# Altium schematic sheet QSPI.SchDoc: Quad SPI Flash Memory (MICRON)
size A4; Date: 29-OCT-2015; Author: A.B; CompanyName: STMicroelectronics; Organization: MCD/TOOLS/GNB; Address1: 12, Rue Jules HOROWITZ; Address2: 38019 Grenoble; Address3: FRANCE; DocumentNumber: MB1225; Revision: B-01; SheetNumber: 6; SheetTotal: 12; Project: STM32F769I-DISCO
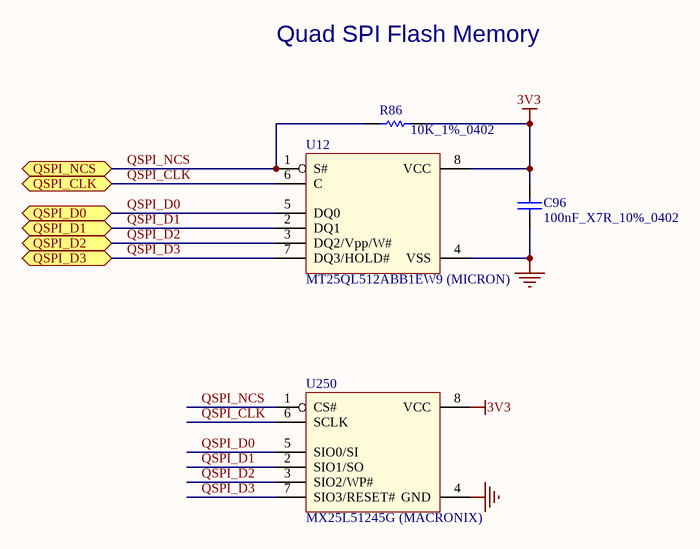
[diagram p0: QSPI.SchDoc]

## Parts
C96  100nF_X7R_10%_0402  [0402C]
R86  10K_1%_0402  [0402R]
U12  MT25QL512ABB1EW9 (MICRON)  [DFN8_1R27_6X8_TP4R8X5R16]
U250  MX25L51245G (MACRONIX)  [SON8_1R27_6X8]

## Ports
QSPI_CLK, QSPI_D0, QSPI_D1, QSPI_D2, QSPI_D3, QSPI_NCS

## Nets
3V3: C96.2 R86.2 U12.8(VCC) U250.8(VCC)
GND: C96.1 U12.4(VSS) U250.4(GND)
QSPI_CLK: U12.6(C) U250.6(SCLK) ; port QSPI_CLK
QSPI_D0: U12.5(DQ0) U250.5(SIO0/SI) ; port QSPI_D0
QSPI_D1: U12.2(DQ1) U250.2(SIO1/SO) ; port QSPI_D1
QSPI_D2: U12.3(DQ2/Vpp/W#) U250.3(SIO2/WP#) ; port QSPI_D2
QSPI_D3: U12.7(DQ3/HOLD#) U250.7(SIO3/RESET#) ; port QSPI_D3
QSPI_NCS: R86.1 U12.1(S#) U250.1(CS#) ; port QSPI_NCS

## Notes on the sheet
- Quad SPI Flash Memory

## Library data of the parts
C96 = Cap_100nF_X7R_10%_0402: Capacitor,100nF,16V,X7R,10%,0402,YAGEO; Manuf_Part_1: CC0402KRX7R7BB104
R86 = Res_10K_1%_0402: Resistor,10K,0402,1%,YAGEO; Manuf_Part_1: RC0402FR-0710KL
U12 = MT25QL512ABB1EW9: 512Mb, 3V, Multiple I/O Serial Flash Memory, Quad/Dual; Manuf_Part_2: N25Q512A13GF840E; Manuf_Part_1: MT25QL512ABB1EW9-0SIT; ECCN_US/EU: 3A991/NEC; Provided: ST; Ref St: xxxxxxxx; Note: MX25L51245GZ2I-08G can also be use but with a different footprint; Fitted: NO
U250 = MX25L51245G: 512Mb, 3V, Multiple I/O Serial Flash Memory, Quad/Dual; Manuf_Part_1: MX25L51245GZ2I-08G; Manuf_Part_2: MX25L51245GZ2I-10G; ECCN_US/EU: 3A991/NEC; Provided: Sub Co; Ref St: xxxxxxxxxx; Note: MT25QL512ABB1EW9 can be also used but with a different footprint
